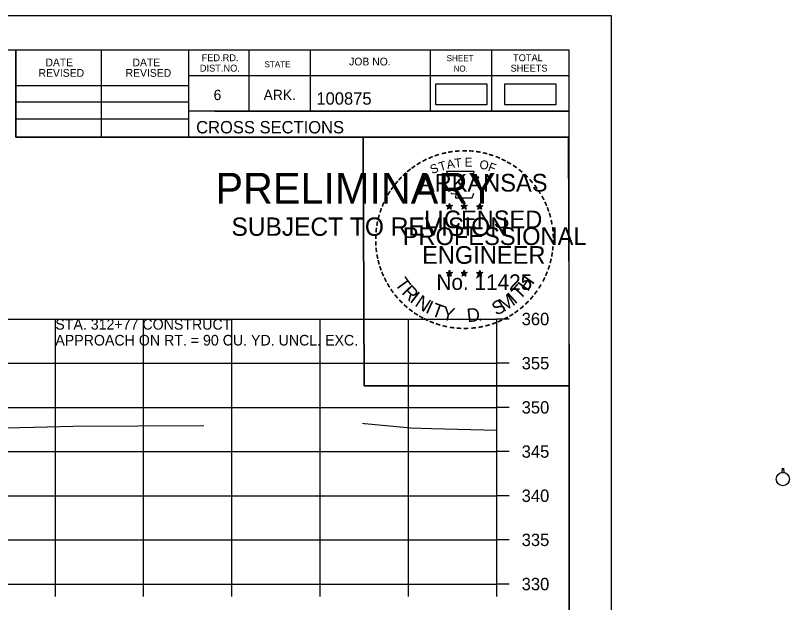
# Model space of a CAD drawing. Extents: x 1368122 to 1710785, y 373130 to 557566.
# Drawn here: x 1369451 to 1369538.7, y 374770.6 to 374837 of the extents above; entities that cross this region are included whole.
import ezdxf

# ---------------------------------------------------------------- set-up
doc = ezdxf.new("R2010")
doc.units = 0
for name, color, linetype in [('R_Axis', 7, 'Continuous'), ('R_Axis Annot', 7, 'Continuous'), ('R_Border', 7, 'Continuous'), ('R_Border PE', 7, 'Continuous'), ('R_Border Prem', 7, 'Continuous'), ('R_Drive', 7, 'Continuous'), ('R_Exist Surface', 7, 'Continuous'), ('R_Grid', 7, 'Continuous'), ('R_No Plot', 7, 'Continuous'), ('R_Water', 7, 'Continuous'), ('R_Water Annot', 7, 'Continuous')]:
    doc.layers.add(name, color=color, linetype=linetype)

msp = doc.modelspace()

# ---------------------------------------------------------------- linework, layer by layer
at = {"layer": 'R_Axis'}
for p, q in [((1369505.561, 374772.675), (1369505.561, 374802.675)), ((1369506.961, 374802.675), (1369505.561, 374802.675)), ((1369506.961, 374797.675), (1369505.561, 374797.675)), ((1369506.961, 374792.675), (1369505.561, 374792.675)), ((1369506.961, 374787.675), (1369505.561, 374787.675)), ((1369506.961, 374782.675), (1369505.561, 374782.675)), ((1369506.961, 374777.675), (1369505.561, 374777.675)), ((1369205.561, 374772.675), (1369505.561, 374772.675)), ((1369455.561, 374771.275), (1369455.561, 374772.675)), ((1369465.561, 374771.275), (1369465.561, 374772.675)), ((1369475.561, 374771.275), (1369475.561, 374772.675)), ((1369485.561, 374771.275), (1369485.561, 374772.675)), ((1369495.561, 374771.275), (1369495.561, 374772.675)), ((1369505.561, 374771.275), (1369505.561, 374772.675)), ((1369506.961, 374772.675), (1369505.561, 374772.675))]:
    msp.add_line(p, q, dxfattribs=at)
at = {"layer": 'R_Border'}
for p, q in [((1369197.561, 374833.135), (1369513.741, 374833.135)), ((1369451.101, 374823.255), (1369451.101, 374833.135)), ((1369460.781, 374823.255), (1369460.781, 374833.135)), ((1369470.641, 374833.135), (1369470.641, 374823.255)), ((1369477.481, 374833.135), (1369477.481, 374826.195)), ((1369484.421, 374833.135), (1369484.421, 374826.195)), ((1369498.001, 374833.135), (1369498.001, 374826.195)), ((1369504.941, 374833.135), (1369504.941, 374826.195)), ((1369513.741, 374627.675), (1369513.741, 374833.135)), ((1369513.741, 374830.195), (1369470.641, 374830.195)), ((1369513.741, 374830.215), (1369513.741, 374830.215)), ((1369451.101, 374829.115), (1369470.641, 374829.115)), ((1369451.101, 374827.255), (1369470.641, 374827.255)), ((1369513.741, 374826.195), (1369470.641, 374826.195)), ((1369473.601, 374826.195), (1369513.741, 374826.195)), ((1369451.101, 374825.315), (1369470.641, 374825.315)), ((1369513.741, 374823.255), (1369451.101, 374823.255))]:
    msp.add_line(p, q, dxfattribs=at)
at = {"layer": 'R_Border PE'}
for p, q in [((1369500.174, 374815.765), (1369500.133, 374815.513)), ((1369500.174, 374815.4), (1369500.174, 374815.765)), ((1369500.174, 374815.765), (1369500.223, 374815.515)), ((1369501.844, 374815.765), (1369501.803, 374815.513)), ((1369501.844, 374815.4), (1369501.844, 374815.765)), ((1369501.844, 374815.765), (1369501.893, 374815.515)), ((1369503.608, 374815.753), (1369503.567, 374815.501)), ((1369503.608, 374815.388), (1369503.608, 374815.753)), ((1369503.608, 374815.753), (1369503.657, 374815.503)), ((1369499.825, 374815.511), (1369500.174, 374815.4)), ((1369499.825, 374815.511), (1369500.078, 374815.466)), ((1369499.825, 374815.511), (1369500.062, 374815.389)), ((1369499.958, 374815.103), (1369500.174, 374815.4)), ((1369499.958, 374815.103), (1369500.084, 374815.347)), ((1369499.958, 374815.103), (1369500.172, 374815.32)), ((1369500.387, 374815.103), (1369500.172, 374815.317)), ((1369500.521, 374815.511), (1369500.174, 374815.4)), ((1369500.387, 374815.103), (1369500.174, 374815.4)), ((1369500.521, 374815.511), (1369500.235, 374815.462)), ((1369500.387, 374815.103), (1369500.25, 374815.394)), ((1369500.521, 374815.511), (1369500.317, 374815.409)), ((1369501.495, 374815.511), (1369501.844, 374815.4)), ((1369501.495, 374815.511), (1369501.748, 374815.466)), ((1369501.495, 374815.511), (1369501.732, 374815.389)), ((1369501.628, 374815.103), (1369501.844, 374815.4)), ((1369501.628, 374815.103), (1369501.754, 374815.347)), ((1369501.628, 374815.103), (1369501.842, 374815.32)), ((1369502.057, 374815.103), (1369501.842, 374815.317)), ((1369502.191, 374815.511), (1369501.844, 374815.4)), ((1369502.057, 374815.103), (1369501.844, 374815.4)), ((1369502.191, 374815.511), (1369501.905, 374815.462)), ((1369502.057, 374815.103), (1369501.92, 374815.394)), ((1369502.191, 374815.511), (1369501.987, 374815.409)), ((1369503.259, 374815.499), (1369503.608, 374815.388)), ((1369503.259, 374815.499), (1369503.512, 374815.454)), ((1369503.259, 374815.499), (1369503.496, 374815.377)), ((1369503.392, 374815.091), (1369503.608, 374815.388)), ((1369503.392, 374815.091), (1369503.518, 374815.335)), ((1369503.392, 374815.091), (1369503.606, 374815.308)), ((1369503.821, 374815.091), (1369503.606, 374815.305)), ((1369503.955, 374815.499), (1369503.608, 374815.388)), ((1369503.821, 374815.091), (1369503.608, 374815.388)), ((1369503.955, 374815.499), (1369503.669, 374815.45)), ((1369503.821, 374815.091), (1369503.684, 374815.382)), ((1369503.955, 374815.499), (1369503.751, 374815.397)), ((1369499.821, 374807.938), (1369500.17, 374807.827)), ((1369499.821, 374807.938), (1369500.074, 374807.893)), ((1369499.821, 374807.938), (1369500.058, 374807.816)), ((1369499.954, 374807.53), (1369500.17, 374807.827)), ((1369500.17, 374808.192), (1369500.129, 374807.94)), ((1369500.17, 374807.827), (1369500.17, 374808.192)), ((1369500.17, 374808.192), (1369500.219, 374807.942)), ((1369500.517, 374807.938), (1369500.17, 374807.827)), ((1369500.383, 374807.53), (1369500.17, 374807.827)), ((1369500.517, 374807.938), (1369500.231, 374807.889)), ((1369500.383, 374807.53), (1369500.246, 374807.821)), ((1369500.517, 374807.938), (1369500.313, 374807.836)), ((1369501.49, 374807.938), (1369501.839, 374807.827)), ((1369501.49, 374807.938), (1369501.743, 374807.893)), ((1369501.49, 374807.938), (1369501.727, 374807.816)), ((1369501.623, 374807.53), (1369501.839, 374807.827)), ((1369501.839, 374808.192), (1369501.798, 374807.94)), ((1369501.839, 374807.827), (1369501.839, 374808.192)), ((1369501.839, 374808.192), (1369501.888, 374807.942)), ((1369502.186, 374807.938), (1369501.839, 374807.827)), ((1369502.052, 374807.53), (1369501.839, 374807.827)), ((1369502.186, 374807.938), (1369501.9, 374807.889)), ((1369502.052, 374807.53), (1369501.915, 374807.821)), ((1369502.186, 374807.938), (1369501.982, 374807.836)), ((1369503.257, 374807.928), (1369503.606, 374807.817)), ((1369503.257, 374807.928), (1369503.51, 374807.883)), ((1369503.257, 374807.928), (1369503.494, 374807.806)), ((1369503.39, 374807.52), (1369503.606, 374807.817)), ((1369503.606, 374808.182), (1369503.565, 374807.93)), ((1369503.606, 374807.817), (1369503.606, 374808.182)), ((1369503.606, 374808.182), (1369503.655, 374807.932)), ((1369503.953, 374807.928), (1369503.606, 374807.817)), ((1369503.819, 374807.52), (1369503.606, 374807.817)), ((1369503.953, 374807.928), (1369503.667, 374807.879)), ((1369503.819, 374807.52), (1369503.682, 374807.811)), ((1369503.953, 374807.928), (1369503.749, 374807.826)), ((1369499.954, 374807.53), (1369500.08, 374807.774)), ((1369499.954, 374807.53), (1369500.168, 374807.747)), ((1369500.383, 374807.53), (1369500.168, 374807.744)), ((1369501.623, 374807.53), (1369501.749, 374807.774)), ((1369501.623, 374807.53), (1369501.837, 374807.747)), ((1369502.052, 374807.53), (1369501.837, 374807.744)), ((1369503.39, 374807.52), (1369503.516, 374807.764)), ((1369503.39, 374807.52), (1369503.604, 374807.737)), ((1369503.819, 374807.52), (1369503.604, 374807.734))]:
    msp.add_line(p, q, dxfattribs=at)
for points in [[(1369499.866, 374819.389), (1369500.135, 374818.562)], [(1369503.377, 374818.467), (1369503.519, 374818.751), (1369502.834, 374818.727), (1369502.982, 374819.389), (1369499.866, 374819.389)], [(1369500.358, 374816.966), (1369500.358, 374816.879), (1369500.921, 374816.86), (1369500.867, 374816.387), (1369502.737, 374816.387), (1369502.938, 374816.923)], [(1369500.174, 374815.765), (1369500.387, 374815.103), (1369499.825, 374815.511), (1369500.521, 374815.511), (1369499.958, 374815.103), (1369500.174, 374815.765)], [(1369501.844, 374815.765), (1369502.057, 374815.103), (1369501.495, 374815.511), (1369502.191, 374815.511), (1369501.628, 374815.103), (1369501.844, 374815.765)], [(1369503.608, 374815.753), (1369503.821, 374815.091), (1369503.259, 374815.499), (1369503.955, 374815.499), (1369503.392, 374815.091), (1369503.608, 374815.753)], [(1369500.17, 374808.192), (1369500.383, 374807.53), (1369499.821, 374807.938), (1369500.517, 374807.938), (1369499.954, 374807.53), (1369500.17, 374808.192)], [(1369501.839, 374808.192), (1369502.052, 374807.53), (1369501.49, 374807.938), (1369502.186, 374807.938), (1369501.623, 374807.53), (1369501.839, 374808.192)], [(1369503.606, 374808.182), (1369503.819, 374807.52), (1369503.257, 374807.928), (1369503.953, 374807.928), (1369503.39, 374807.52), (1369503.606, 374808.182)]]:
    msp.add_lwpolyline(points, dxfattribs=at)
for centre, radius in [((1369500.173, 374815.399), 0.172), ((1369500.173, 374815.399), 0.145), ((1369500.173, 374815.399), 0.116), ((1369500.173, 374815.399), 0.0991), ((1369500.173, 374815.399), 0.0747), ((1369500.173, 374815.399), 0.0495), ((1369500.173, 374815.399), 0.0296), ((1369501.843, 374815.399), 0.172), ((1369501.843, 374815.399), 0.145), ((1369501.843, 374815.399), 0.116), ((1369501.843, 374815.399), 0.0991), ((1369501.843, 374815.399), 0.0747), ((1369501.843, 374815.399), 0.0495), ((1369501.843, 374815.399), 0.0296), ((1369503.607, 374815.387), 0.172), ((1369503.607, 374815.387), 0.145), ((1369503.607, 374815.387), 0.116), ((1369503.607, 374815.387), 0.0991), ((1369503.607, 374815.387), 0.0747), ((1369503.607, 374815.387), 0.0495), ((1369503.607, 374815.387), 0.0296), ((1369500.169, 374807.826), 0.172), ((1369500.169, 374807.826), 0.145), ((1369500.169, 374807.826), 0.116), ((1369500.169, 374807.826), 0.0991), ((1369500.169, 374807.826), 0.0747), ((1369500.169, 374807.826), 0.0495), ((1369500.169, 374807.826), 0.0296), ((1369501.838, 374807.826), 0.172), ((1369501.838, 374807.826), 0.145), ((1369501.838, 374807.826), 0.116), ((1369501.838, 374807.826), 0.0991), ((1369501.838, 374807.826), 0.0747), ((1369501.838, 374807.826), 0.0495), ((1369501.838, 374807.826), 0.0296), ((1369503.605, 374807.816), 0.172), ((1369503.605, 374807.816), 0.145), ((1369503.605, 374807.816), 0.116), ((1369503.605, 374807.816), 0.0991), ((1369503.605, 374807.816), 0.0747), ((1369503.605, 374807.816), 0.0495), ((1369503.605, 374807.816), 0.0296)]:
    msp.add_circle(centre, radius, dxfattribs=at)
at = {"layer": 'R_Drive'}
for points in [[(1369498.614, 374826.964), (1369504.447, 374826.964), (1369504.447, 374829.274), (1369498.614, 374829.274)], [(1369506.424, 374826.964), (1369512.257, 374826.964), (1369512.257, 374829.274), (1369506.424, 374829.274)]]:
    msp.add_lwpolyline(points, close=True, dxfattribs=at)
at = {"layer": 'R_Exist Surface'}
for points in [[(1369404.828, 374788.012), (1369416.249, 374790.706), (1369416.721, 374790.725), (1369419.135, 374790.842), (1369419.407, 374790.84), (1369419.647, 374790.839), (1369419.796, 374790.611), (1369420.03, 374790.382), (1369420.228, 374790.372), (1369422.725, 374790.377), (1369429.021, 374790.46), (1369431.835, 374790.439), (1369434.079, 374790.427), (1369441.956, 374790.395), (1369443.224, 374790.402), (1369449.97, 374790.349), (1369454.637, 374790.484), (1369457.547, 374790.556), (1369472.37, 374790.603)], [(1369490.32, 374790.87), (1369490.559, 374790.86), (1369492.596, 374790.668), (1369495.792, 374790.376), (1369496.926, 374790.315), (1369498.16, 374790.286), (1369505.561, 374790.087)]]:
    msp.add_lwpolyline(points, dxfattribs=at)
at = {"layer": 'R_Grid'}
for p, q in [((1369205.561, 374802.675), (1369505.561, 374802.675)), ((1369455.561, 374772.675), (1369455.561, 374802.675)), ((1369465.561, 374772.675), (1369465.561, 374802.675)), ((1369475.561, 374772.675), (1369475.561, 374802.675)), ((1369485.561, 374772.675), (1369485.561, 374802.675)), ((1369495.561, 374772.675), (1369495.561, 374802.675)), ((1369505.561, 374772.675), (1369505.561, 374802.675)), ((1369205.561, 374797.675), (1369505.561, 374797.675)), ((1369205.561, 374792.675), (1369505.561, 374792.675)), ((1369205.561, 374787.675), (1369505.561, 374787.675)), ((1369205.561, 374782.675), (1369505.561, 374782.675)), ((1369205.561, 374777.675), (1369505.561, 374777.675)), ((1369205.561, 374772.675), (1369505.561, 374772.675))]:
    msp.add_line(p, q, dxfattribs=at)
at = {"layer": 'R_No Plot'}
for p, q in [((1369185.16, 374837.03), (1369518.493, 374837.03)), ((1369489.775, 374800.8), (1369489.775, 374800.8))]:
    msp.add_line(p, q, dxfattribs=at)
for points in [[(1369185.153, 374837.03), (1369518.493, 374837.03), (1369518.493, 374623.692), (1369185.153, 374623.692)], [(1369431.481, 374833.135), (1369451.101, 374833.135), (1369451.101, 374823.255), (1369467.213, 374823.255), (1369490.412, 374823.255), (1369490.533, 374795.099), (1369513.741, 374795.099), (1369513.741, 374627.675), (1369197.561, 374627.675), (1369197.561, 374833.135)], [(1369490.412, 374823.255), (1369513.62, 374823.255), (1369513.741, 374795.099), (1369490.533, 374795.099)]]:
    msp.add_lwpolyline(points, close=True, dxfattribs=at)
msp.add_circle((1369537.929, 374784.557), 0.755, dxfattribs=at)
at = {"layer": 'R_Water'}
msp.add_line((1369538.002, 374785.803), (1369538.058, 374785.296), dxfattribs=at)
msp.add_lwpolyline([(1369537.855, 374785.803), (1369537.799, 374785.295)], dxfattribs=at)
msp.add_circle((1369537.929, 374784.557), 0.75, dxfattribs=at)

# ---------------------------------------------------------------- texts
at = {"layer": 'R_Axis Annot'}
for s, p in [('360', (1369508.361, 374801.975)), ('355', (1369508.361, 374796.975)), ('350', (1369508.361, 374791.975)), ('345', (1369508.361, 374786.975)), ('340', (1369508.361, 374781.975)), ('335', (1369508.361, 374776.975)), ('330', (1369508.361, 374771.975))]:
    msp.add_text(s, height=1.4, dxfattribs=at).set_placement(p)
at = {"layer": 'R_Border'}
for s, height, p in [('FED.RD.', 0.7819, (1369472.121, 374831.855)), ('SHEET', 0.684, (1369499.861, 374831.855)), ('TOTAL', 0.7819, (1369507.381, 374831.855)), ('DATE', 0.8792, (1369454.438, 374831.272)), ('DATE', 0.8792, (1369464.298, 374831.272)), ('DIST.NO.', 0.7819, (1369471.921, 374830.675)), ('STATE', 0.684, (1369479.241, 374831.175)), ('JOB NO.', 0.8792, (1369488.821, 374831.375)), ('SHEETS', 0.7819, (1369507.101, 374830.675)), ('REVISED', 0.8792, (1369453.658, 374830.092)), ('REVISED', 0.8792, (1369463.518, 374830.092)), ('NO.', 0.684, (1369500.641, 374830.675)), ('6', 1.172, (1369473.481, 374827.455)), ('ARK.', 1.1723, (1369479.141, 374827.455)), ('100875', 1.4, (1369485.116, 374826.935)), ('CROSS SECTIONS', 1.4, (1369471.504, 374823.686))]:
    msp.add_text(s, height=height, rotation=360, dxfattribs=at).set_placement(p)
at = {"layer": 'R_Border PE'}
for s, height, rotation, p in [('-', 1.6, 24.30721, (1369497.98, 374820.247)), ('-', 1.6, 19.17608, (1369498.614, 374820.516)), ('-', 1.6, 13.63015, (1369499.364, 374820.757)), ('-', 1.6, 10.21935, (1369500.042, 374820.919)), ('-', 1.6, 5.89682, (1369500.771, 374821.029)), ('-', 1.6, 0.18623, (1369501.543, 374821.101)), ('-', 1.6, 357.74304, (1369502.266, 374821.088)), ('-', 1.6, 352.16172, (1369503.01, 374821.032)), ('-', 1.6, 347.20489, (1369503.729, 374820.918)), ('-', 1.6, 342.3362, (1369504.364, 374820.763)), ('-', 1.6, 337.85509, (1369505.099, 374820.54)), ('-', 1.6, 36.23174, (1369496.172, 374819.165)), ('-', 1.6, 34.06357, (1369496.75, 374819.56)), ('-', 1.6, 28.79182, (1369497.347, 374819.93)), ('S', 1, 21.59401, (1369498.221, 374819.067)), ('T', 1, 16.4036, (1369499.135, 374819.398)), ('A', 1, 11.21318, (1369499.961, 374819.649)), ('T', 1, 6.02276, (1369500.81, 374819.815)), ('E', 1, 0.83234, (1369501.915, 374819.925)), ('O', 1, 350.4515, (1369503.519, 374819.715)), ('F', 1, 340.07066, (1369504.473, 374819.487)), ('-', 1.6, 334.12109, (1369505.73, 374820.269)), ('-', 1.6, 329.64089, (1369506.309, 374819.986)), ('-', 1.6, 325.86266, (1369506.952, 374819.625)), ('-', 1.6, 42.96224, (1369495.263, 374818.37)), ('-', 1.6, 38.95066, (1369495.696, 374818.787)), ('-', 1.6, 320.52971, (1369507.562, 374819.199)), ('-', 1.6, 50.61417, (1369494.412, 374817.406)), ('-', 1.6, 48.42305, (1369494.815, 374817.892)), ('ARKANSAS', 2, 360, (1369496.719, 374817.101)), ('-', 1.6, 315.57859, (1369508.161, 374818.711)), ('-', 1.6, 309.87973, (1369508.73, 374818.161)), ('-', 1.6, 54.23247, (1369493.999, 374816.839)), ('-', 1.6, 306.65218, (1369509.255, 374817.559)), ('-', 1.6, 62.87135, (1369493.361, 374815.698)), ('-', 1.6, 58.07063, (1369493.674, 374816.312)), ('-', 1.4, 303.67529, (1369509.741, 374816.991)), ('-', 1.6, 299.66835, (1369510.06, 374816.384)), ('-', 1.6, 67.77427, (1369493.102, 374815.087)), ('-', 1.6, 294.66279, (1369510.384, 374815.772)), ('-', 1.6, 72.39447, (1369492.883, 374814.457)), ('LICENSED', 2, 360, (1369497.317, 374812.952)), ('DWB', 0.01, 360, (1369500.162, 374815.394)), ('DWB', 0.01, 360, (1369501.831, 374815.394)), ('DWB', 0.01, 360, (1369503.596, 374815.384)), ('-', 1.6, 290.57283, (1369510.641, 374815.195)), ('-', 1.6, 75.46096, (1369492.686, 374813.743)), ('-', 1.6, 285.12326, (1369510.875, 374814.615)), ('-', 1.6, 81.20126, (1369492.554, 374813.03)), ('PROFESSIONAL', 2, 360, (1369494.893, 374811.048)), ('-', 1.6, 280.54934, (1369511.075, 374813.873)), ('-', 1.6, 276.59616, (1369511.237, 374813.105)), ('-', 1.6, 89.06224, (1369492.453, 374811.638)), ('-', 1.6, 85.18634, (1369492.478, 374812.339)), ('-', 1.6, 274.33011, (1369511.297, 374812.383)), ('-', 1.6, 94.19588, (1369492.488, 374810.913)), ('-', 1.6, 269.94067, (1369511.331, 374811.751)), ('-', 1.6, 98.94793, (1369492.56, 374810.246)), ('ENGINEER', 2, 360, (1369497.08, 374808.923)), ('-', 1.6, 263.5172, (1369511.312, 374811.085)), ('-', 1.6, 101.71495, (1369492.695, 374809.513)), ('-', 1.6, 260.99529, (1369511.241, 374810.431)), ('-', 1.6, 105.45785, (1369492.857, 374808.918)), ('-', 1.6, 109.08742, (1369493.072, 374808.287)), ('-', 1.6, 252.86809, (1369510.95, 374809.033)), ('-', 1.6, 255.7626, (1369511.131, 374809.753)), ('-', 1.6, 114.06432, (1369493.326, 374807.691)), ('DWB', 0.01, 360, (1369500.158, 374807.822)), ('DWB', 0.01, 360, (1369501.827, 374807.822)), ('DWB', 0.01, 360, (1369503.594, 374807.812)), ('-', 1.6, 247.88866, (1369510.727, 374808.36)), ('-', 1.6, 115.72885, (1369493.631, 374807.073)), ('T', 1.54, 306.04056, (1369493.93, 374806.665)), ('No. 11425', 1.757, 360, (1369498.708, 374805.972)), ('H', 1.54, 54.60883, (1369509.05, 374805.7)), ('-', 1.6, 244.61971, (1369510.465, 374807.731)), ('-', 1.6, 120.44712, (1369493.988, 374806.487)), ('-', 1.6, 125.89344, (1369494.391, 374805.926)), ('R', 1.54, 314.00497, (1369494.693, 374805.617)), ('T', 1.54, 46.64442, (1369508.161, 374804.757)), ('-', 1.6, 239.07125, (1369510.071, 374806.979)), ('-', 1.6, 130.71812, (1369494.853, 374805.374)), ('I', 1.54, 321.96938, (1369495.593, 374804.685)), ('N', 1.54, 326.50021, (1369496.16, 374804.213)), ('M', 1.54, 32.65632, (1369506.315, 374803.432)), ('I', 1.54, 42.11359, (1369507.599, 374804.279)), ('-', 1.6, 231.25377, (1369509.239, 374805.76)), ('-', 1.6, 233.84524, (1369509.669, 374806.326)), ('-', 1.6, 134.22381, (1369495.37, 374804.829)), ('-', 1.6, 138.93382, (1369495.895, 374804.365)), ('I', 1.54, 335.36034, (1369497.368, 374803.427)), ('T', 1.54, 339.89117, (1369498.029, 374803.1)), ('S', 1.54, 26.9312, (1369505.476, 374803.026)), ('-', 1.6, 225.76533, (1369508.76, 374805.196)), ('-', 1.6, 144.64634, (1369496.451, 374803.959)), ('-', 1.6, 148.08978, (1369497.012, 374803.588)), ('Y', 1.54, 347.85558, (1369499.246, 374802.654)), ('D', 1.54, 6.39691, (1369502.231, 374802.296)), ('-', 1.6, 215.73633, (1369507.689, 374804.215)), ('-', 1.6, 221.08509, (1369508.238, 374804.687)), ('-', 1.6, 151.57039, (1369497.591, 374803.263)), ('-', 1.6, 154.60019, (1369498.113, 374803.016)), ('.', 1.54, 13.76417, (1369503.423, 374802.423)), ('-', 1.6, 204.25161, (1369505.973, 374803.163)), ('-', 1.6, 207.35684, (1369506.597, 374803.482)), ('-', 1.6, 212.24909, (1369507.155, 374803.828)), ('-', 1.6, 158.56121, (1369498.737, 374802.762)), ('-', 1.6, 162.79826, (1369499.424, 374802.549)), ('-', 1.6, 167.55551, (1369500.139, 374802.385)), ('-', 1.6, 173.11546, (1369500.911, 374802.275)), ('-', 1.6, 176.51827, (1369501.659, 374802.222)), ('-', 1.6, 181.59176, (1369502.403, 374802.241)), ('-', 1.6, 185.81666, (1369503.212, 374802.317)), ('-', 1.6, 191.28576, (1369503.948, 374802.449)), ('-', 1.6, 195.47429, (1369504.677, 374802.648)), ('-', 1.6, 200.71842, (1369505.354, 374802.89))]:
    msp.add_text(s, height=height, rotation=rotation, dxfattribs=at).set_placement(p)
at = {"layer": 'R_Border Prem'}
for s, height, p in [('PRELIMINARY', 3.5, (1369473.692, 374815.719)), ('DWB', 0.01, (1369474.438, 374817.568)), ('SUBJECT TO REVISION', 2.07511, (1369475.501, 374812.09))]:
    msp.add_text(s, height=height, rotation=360, dxfattribs=at).set_placement(p)
at = {"layer": 'R_Water Annot'}
for s, p in [('STA. 312+77 CONSTRUCT', (1369455.561, 374801.475)), ('APPROACH ON RT. = 90 CU. YD. UNCL. EXC.', (1369455.561, 374799.675))]:
    msp.add_text(s, height=1.2, dxfattribs=at).set_placement(p)

doc.saveas('drawing.dxf')
